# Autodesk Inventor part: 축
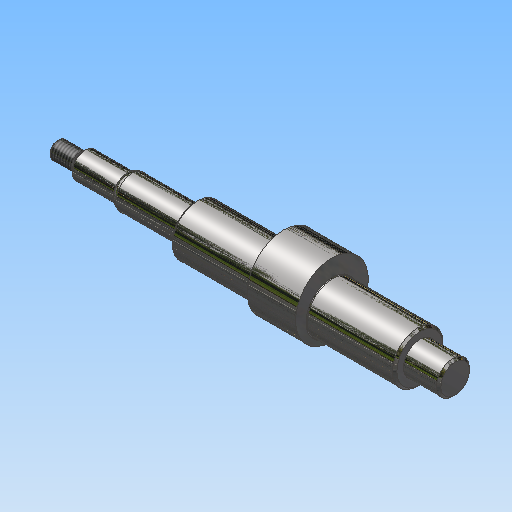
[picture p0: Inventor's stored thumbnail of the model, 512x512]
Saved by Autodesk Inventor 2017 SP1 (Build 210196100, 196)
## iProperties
Created: 2015-12
Part Number: 축
Document SubType Name: Modeling
Designer: mdu
Density: 7.86 g/cm^3
Material: 강철, 연강
Mass: 494.666 g
Surface Area: 129.298 cm^2
Volume: 62.9347 cm^3
Appearance: 반광택
Author: mdu
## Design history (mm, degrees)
sketch "스케치1"
  geometry: L1 (62, 100.9)-(62, 67.1) reference; L2 (51, 101.2)-(51, 84) reference; L3 (-51, 84)-(-51, 101.2) reference; L4 (-62, 67.1)-(-62, 100.9) reference; L5 (-51.6, 91.5)-(-61.4, 91.5) reference; L6 (51.6, 91.5)-(61.4, 91.5) reference; L7 (67, 84)-(-114, 84); L8 (-77, 64.201)-(-77, 103.799) reference; L9 (67, 84)-(67, 91.5); L10 (67, 91.5)-(51, 91.5); L11 (51, 91.5)-(51, 95.5); L12 (51, 95.5)-(-51, 95.5); L13 (-51, 95.5)-(-51, 91.5); L14 (-51, 91.5)-(-82, 91.5); L15 (-82, 91.5)-(-82, 90); L16 (-82, 90)-(-102, 90); L17 (-102, 90)-(-102, 87); L18 (-103.5, 88)-(-114, 88); L19 (-114, 88)-(-114, 84); L20 (-102, 87)-(-103.5, 87); L21 (-103.5, 87)-(-103.5, 88); 2 further points
  constraints: 32 end point, 7 parallel, 6 point on line, 5 perpendicular, 2 collinear, 2 horizontal, 1 midpoint, 4 other
  dimensions: "d0" = 5 distance from line of L7.start L1; "d2" = 5 distance between parallel lines of L15 L8; "d3" = 23 diameter of L12 L7; "d4" = 12 diameter of L16 L7; "d5" = 1.5 distance of L17.end L20.end; "d6" = 6 diameter of L20 L7; "d7" = 20 distance of L15.end L16.end; "d8" = 12 distance between parallel lines of L17 L19; "d9" = 8 diameter of L18 L7
revolve "회전1" sketch "스케치1" stored, may be unused: angle "d10" = 90 deg
sketch "스케치2"
  geometry: C1 r 11.5 at (84, 0) reference; C2 r 11.5 at (84, 0) reference; C3 r 16.5 at (87, 0); 1 further point
  constraints: 1 centre point, 1 horizontal alignment
  dimensions: "d11" = 33 diameter of C3; "d12" = 3 distance of C3.centre C1.centre
extrude "돌출1" join sketch "스케치2" stored distance "d13" = 22; taper "d14" = 0 deg
chamfer "모따기1" distance "d15" = 1; stored, may be unused: second distance "d16" = 2, angle "d17" = 45 deg
feature "스레드1" dims "d18" = 10, "d19" = 0
node "작업 평면1"
sketch "스케치3"
  geometry: L1 (-5, -2)-(3, -2); L2 (3, 2)-(-5, 2); L3 (-10, -5)-(-10, 5) reference; A1 r 2 centre (3, 0) between (3, -2) and (3, 2); A2 r 2 centre (-5, 0) between (-5, 2) and (-5, -2); 2 further points
  constraints: 4 end point, 4 point on circle, 4 tangent, 2 centre point, 1 horizontal, 1 horizontal alignment, 1 midpoint, 1 parallel
  dimensions: "d20" = 4 distance between parallel lines of L1 L2; "d21" = 12 dimension on A1 A2; "d22" = 3 distance edge to line of A2 L3
extrude "돌출2" cut sketch "스케치3" distance "d23" = 2.5; taper "d24" = 0 deg
fillet "모깎기1" dims "d25" = 0.3
fillet "모깎기2" dims "d26" = 3
node "솔리드1"
node "참조1"
node "참조2"
node "참조3"
node "참조4"
node "참조5"
node "투영된 루프1"
